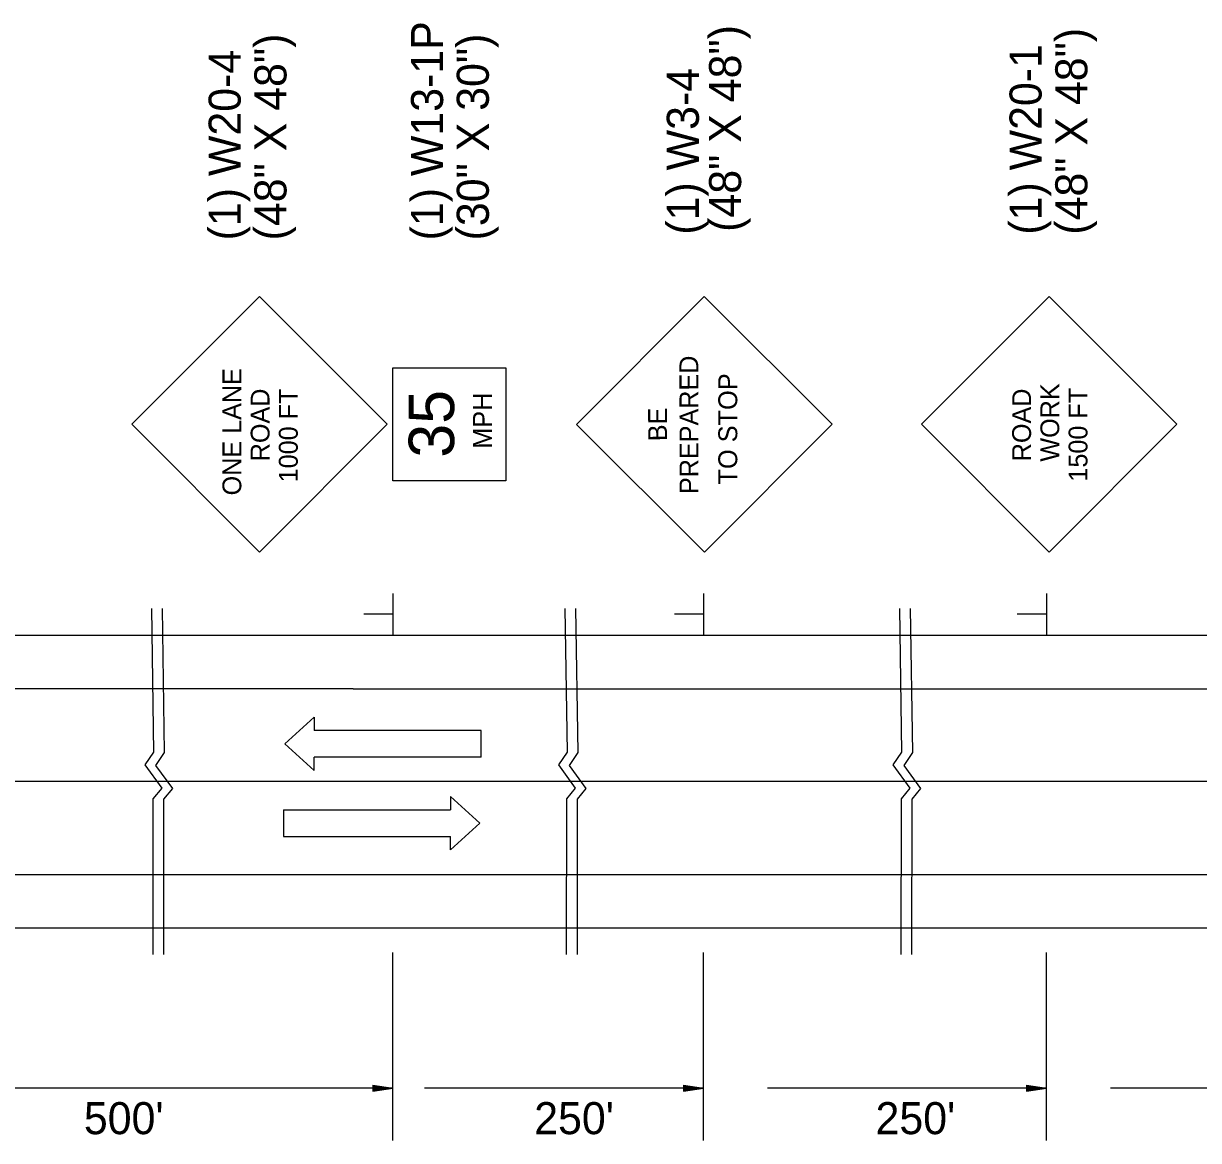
# Model space of a CAD drawing. Extents: x 1806907 to 1812607, y 675071 to 676228.
# Drawn here: x 1809871.3 to 1810091.1, y 675311.3 to 675520.3 of the extents above; entities that cross this region are included whole.
import ezdxf

# ---------------------------------------------------------------- set-up
doc = ezdxf.new("R2010")
doc.units = 0
doc.layers.add('Default', color=7, linetype='Continuous')
doc.layers.add('R_MOT', color=7, linetype='Continuous')

msp = doc.modelspace()

# ---------------------------------------------------------------- linework, layer by layer
at = {"layer": 'Default'}
for p, q in [((1809915.42, 675469.23), (1809891.52, 675445.33)), ((1809915.42, 675469.23), (1809939.3, 675445.33)), ((1809998.58, 675469.23), (1809974.74, 675445.29)), ((1809998.58, 675469.23), (1810022.53, 675445.37)), ((1810063.15, 675469.23), (1810039.25, 675445.33)), ((1810063.15, 675469.23), (1810087.04, 675445.33)), ((1809891.52, 675445.33), (1809915.42, 675421.43)), ((1809939.3, 675445.33), (1809915.42, 675421.43)), ((1809974.74, 675445.29), (1809998.67, 675421.43)), ((1810022.53, 675445.37), (1809998.67, 675421.43)), ((1810039.25, 675445.33), (1810063.15, 675421.43)), ((1810087.04, 675445.33), (1810063.15, 675421.43)), ((1809940.38, 675413.69), (1809940.38, 675405.86)), ((1809998.48, 675413.69), (1809998.48, 675405.86)), ((1810062.64, 675413.69), (1810062.64, 675405.86)), ((1809940.27, 675409.8), (1809934.93, 675409.8)), ((1809998.37, 675409.8), (1809993.03, 675409.8)), ((1810062.53, 675409.8), (1810057.19, 675409.8)), ((1809377.42, 675405.86), (1810285.94, 675405.86)), ((1809932.92, 675395.86), (1809809.88, 675395.86)), ((1809932.92, 675395.86), (1810285.94, 675395.86)), ((1810285.94, 675378.48), (1809843.73, 675378.48)), ((1809815.59, 675361.1), (1809932.92, 675361.1)), ((1809932.92, 675361.1), (1810285.94, 675361.1)), ((1809377.42, 675351.1), (1810285.94, 675351.1)), ((1809940.38, 675311.31), (1809940.38, 675346.52)), ((1809998.48, 675311.31), (1809998.48, 675346.52)), ((1810062.64, 675311.31), (1810062.64, 675346.52)), ((1809936.63, 675321.66), (1809940.38, 675321.1)), ((1809936.63, 675321.66), (1809936.63, 675320.54)), ((1809936.63, 675321.57), (1809939.75, 675321.1)), ((1809936.63, 675321.47), (1809939.11, 675321.1)), ((1809936.63, 675321.38), (1809938.48, 675321.1)), ((1809994.73, 675321.66), (1809998.48, 675321.1)), ((1809994.73, 675321.66), (1809994.73, 675320.54)), ((1809994.73, 675321.57), (1809997.86, 675321.1)), ((1809994.73, 675321.47), (1809997.21, 675321.1)), ((1809994.73, 675321.38), (1809996.59, 675321.1)), ((1810058.89, 675321.66), (1810062.64, 675321.1)), ((1810058.89, 675321.66), (1810058.89, 675320.54)), ((1810058.89, 675321.57), (1810062.02, 675321.1)), ((1810058.89, 675321.47), (1810061.37, 675321.1)), ((1810058.89, 675321.38), (1810060.75, 675321.1)), ((1809940.38, 675321.1), (1809849.64, 675321.1)), ((1809936.63, 675321.28), (1809937.85, 675321.1)), ((1809936.63, 675321.19), (1809937.22, 675321.1)), ((1809936.63, 675320.54), (1809940.38, 675321.1)), ((1809936.63, 675320.91), (1809937.85, 675321.1)), ((1809936.63, 675320.72), (1809939.11, 675321.1)), ((1809936.63, 675320.63), (1809939.75, 675321.1)), ((1809936.63, 675320.82), (1809938.48, 675321.1)), ((1809936.63, 675321.01), (1809937.22, 675321.1)), ((1809998.48, 675321.1), (1809946.29, 675321.1)), ((1809994.73, 675321.28), (1809995.95, 675321.1)), ((1809994.73, 675321.19), (1809995.33, 675321.1)), ((1809994.73, 675320.54), (1809998.48, 675321.1)), ((1809994.73, 675320.91), (1809995.95, 675321.1)), ((1809994.73, 675320.72), (1809997.21, 675321.1)), ((1809994.73, 675320.63), (1809997.86, 675321.1)), ((1809994.73, 675320.82), (1809996.59, 675321.1)), ((1809994.73, 675321.01), (1809995.33, 675321.1)), ((1810062.64, 675321.1), (1810010.45, 675321.1)), ((1810058.89, 675321.28), (1810060.11, 675321.1)), ((1810058.89, 675321.19), (1810059.49, 675321.1)), ((1810058.89, 675320.54), (1810062.64, 675321.1)), ((1810058.89, 675320.91), (1810060.11, 675321.1)), ((1810058.89, 675320.72), (1810061.37, 675321.1)), ((1810058.89, 675320.63), (1810062.02, 675321.1)), ((1810058.89, 675320.82), (1810060.75, 675321.1)), ((1810058.89, 675321.01), (1810059.49, 675321.1)), ((1810126.8, 675321.1), (1810074.62, 675321.1))]:
    msp.add_line(p, q, dxfattribs=at)
msp.add_lwpolyline([(1809940.37, 675434.76), (1809940.37, 675455.89), (1809961.5, 675455.89), (1809961.5, 675434.76)], close=True, dxfattribs=at)
for points in [[(1809895.2, 675410.87), (1809895.61, 675383.99), (1809893.98, 675381.58), (1809897.15, 675377.25), (1809895.48, 675375.25), (1809895.48, 675346.1)], [(1809897.2, 675410.87), (1809897.61, 675383.91), (1809895.98, 675381.5), (1809899.15, 675377.17), (1809897.48, 675375.17), (1809897.48, 675346.1)], [(1809972.55, 675410.87), (1809972.96, 675383.99), (1809971.33, 675381.58), (1809974.5, 675377.25), (1809972.83, 675375.25), (1809972.82, 675346.1)], [(1809974.54, 675410.87), (1809974.95, 675383.91), (1809973.33, 675381.5), (1809976.49, 675377.17), (1809974.83, 675375.17), (1809974.82, 675346.1)], [(1810035.14, 675410.87), (1810035.55, 675383.99), (1810033.93, 675381.58), (1810037.09, 675377.25), (1810035.43, 675375.25), (1810035.42, 675346.1)], [(1810037.14, 675410.87), (1810037.55, 675383.91), (1810035.93, 675381.5), (1810039.09, 675377.17), (1810037.43, 675375.17), (1810037.42, 675346.1)]]:
    msp.add_lwpolyline(points, dxfattribs=at)
at = {"layer": 'R_MOT'}
for p, q in [((1809920.18, 675385.55), (1809925.66, 675390.55)), ((1809925.66, 675390.55), (1809925.66, 675388.05)), ((1809956.88, 675388.05), (1809925.66, 675388.05)), ((1809956.88, 675383.05), (1809956.88, 675388.05)), ((1809925.66, 675380.55), (1809920.18, 675385.55)), ((1809956.88, 675383.05), (1809925.66, 675383.05)), ((1809925.66, 675380.55), (1809925.66, 675383.05)), ((1809951.14, 675375.71), (1809956.62, 675370.71)), ((1809951.14, 675375.71), (1809951.14, 675373.21)), ((1809919.92, 675373.21), (1809951.14, 675373.21)), ((1809919.92, 675373.21), (1809919.92, 675368.21)), ((1809956.62, 675370.71), (1809951.14, 675365.71)), ((1809919.92, 675368.21), (1809951.14, 675368.21)), ((1809951.14, 675365.71), (1809951.14, 675368.21))]:
    msp.add_line(p, q, dxfattribs=at)

# ---------------------------------------------------------------- texts
at = {"layer": 'Default'}
for s, height, rotation, p in [('(1) W13-1P', 6, 90, (1809949.77, 675479.75)), ('(48" X 48")', 6, 90, (1810005.52, 675481.35)), ('(48" X 48")', 6, 90, (1809920.47, 675479.75)), ('(30" X 30")', 6, 90, (1809958.33, 675479.75)), ('(48" X 48")', 6, 90, (1810070.29, 675480.82)), ('(1) W20-4', 6, 90, (1809911.91, 675479.75)), ('(1) W20-1', 6, 90, (1810061.73, 675480.82)), ('(1) W3-4', 6, 90, (1809997.62, 675480.82)), ('PREPARED', 3.521, 90.1003, (1809997.54, 675432.29)), ('ONE LANE', 3.521, 90.0004, (1809912.02, 675432.03)), ('TO STOP', 3.544, 90.0006, (1810004.8, 675434.07)), ('ROAD', 3.52, 90, (1809917.3, 675438.42)), ('1000 FT', 3.522, 90.0006, (1809922.58, 675434.47)), ('35', 8.51, 90, (1809951.84, 675439.1)), ('ROAD', 3.521, 90.0004, (1810059.75, 675438.42)), ('WORK', 3.52, 90, (1810065.03, 675438.35)), ('1500 FT', 3.522, 90.0006, (1810070.31, 675434.61)), ('MPH', 3.522, 90.0006, (1809958.89, 675440.78)), ('BE', 3.521, 90.1004, (1809991.66, 675442.17))]:
    msp.add_text(s, height=height, rotation=rotation, dxfattribs=at).set_placement(p)
for s, p in [("500'", (1809882.57, 675312.49)), ("250'", (1809966.81, 675312.49)), ("250'", (1810030.66, 675312.49))]:
    msp.add_text(s, height=6, dxfattribs=at).set_placement(p)

doc.saveas('drawing.dxf')
